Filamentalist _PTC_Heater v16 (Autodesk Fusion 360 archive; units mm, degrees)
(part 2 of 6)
sketch "Sketch153" plane through (-25.4087, 0, 0) normal (-1, 0, 0) x axis (0, -1, 0)
  line L1 (-131.7787, -103.2462) -> (-131.7787, 82.7538)
  line L2 (-127.2387, -103.2462) -> (-131.7787, -103.2462)
  line L3 (-127.2387, 82.7538) -> (-127.2387, -103.2462)
  line L4 (-131.7787, 82.7538) -> (-127.2387, 82.7538)
  line L5 (-64, 4) -> (-133, 4)
  line L6 (-64, 4.01) -> (-64, 4)
  line L7 (-133, 4.01) -> (-64, 4.01)
  line L8 (-133, 4) -> (-133, 4.01)
  point P6 (-133, 4)
  point P9 (-133, 4.01)
  horizontal L5
  vertical L6
  horizontal L7
  vertical L8
  dimension "d493" distance P6 P9 = 0.01
extrude "Extrude31" cut sketch "Sketch153" profile of L1 L3 L5 L6 L7 L8 against normal blind 160
sketch "Sketch154" plane through (0, 131.7787, 0) normal (0, 1, 0) x axis (-1, 0, 0)
  line L1 (25.4087, 4.01) -> (22.6596, 4.01)
  line L2 (25.4087, 82.7538) -> (25.4087, 4.01)
  line L3 (-106.3913, 102.7538) -> (5.4087, 102.7538)
  line L4 (-126.3913, 41.3578) -> (-126.3913, 82.7538)
  line L5 (-126.1913, 41.3578) -> (-126.3913, 41.3578)
  line L6 (-126.1913, 4.01) -> (-126.1913, 41.3578)
  line L7 (-123.4423, 4.01) -> (-126.1913, 4.01)
  line L8 (18.1577, 4.01) -> (-118.9404, 4.01)
  line L9 (-75.4807, 26.9368) -> (-71.2365, 31.181)
  line L10 (-71.2365, 51.5347) -> (-75.4808, 55.779)
  line L11 (-40.3585, 60.7014) -> (-44.602, 56.4579)
  line L12 (-44.602, 26.2578) -> (-40.3585, 22.0143)
  line L13 (-41.0373, 21.3355) -> (-45.2808, 25.579)
  line L14 (-75.4809, 25.579) -> (-79.7243, 21.3355)
  line L15 (-65.6314, 35.4285) -> (-69.8785, 31.1814)
  line L16 (-50.8832, 31.1814) -> (-55.1303, 35.4285)
  line L17 (-55.1317, 45.9282) -> (-59.7021, 41.3578)
  line L18 (-59.7021, 41.3578) -> (-55.1317, 36.7875)
  line L19 (-70.5573, 31.8602) -> (-66.3102, 36.1073)
  line L20 (-66.3102, 46.6084) -> (-70.5573, 50.8555)
  line L21 (-65.63, 36.7875) -> (-61.0596, 41.3578)
  line L22 (-61.0596, 41.3578) -> (-65.63, 45.9282)
  line L23 (-69.8785, 51.5343) -> (-65.6314, 47.2872)
  line L24 (-55.1303, 47.2872) -> (-50.8832, 51.5343)
  line L25 (-64.9512, 46.607) -> (-60.3808, 42.0366)
  line L26 (-60.3808, 42.0366) -> (-55.8105, 46.607)
  line L27 (-45.2808, 57.1367) -> (-41.0373, 61.3802)
  line L28 (-79.7244, 61.3802) -> (-75.4809, 57.1367)
  line L29 (-74.802, 56.4578) -> (-70.5577, 52.2135)
  line L30 (-50.204, 52.2135) -> (-45.9597, 56.4578)
  line L31 (-55.8105, 36.1087) -> (-60.3808, 40.6791)
  line L32 (-60.3808, 40.6791) -> (-64.9512, 36.1087)
  line L33 (-49.5252, 31.181) -> (-45.281, 26.9368)
  line L34 (-45.2809, 55.779) -> (-49.5252, 51.5347)
  line L35 (-70.5577, 30.5022) -> (-74.8019, 26.258)
  line L36 (-45.9598, 26.258) -> (-50.204, 30.5022)
  line L37 (-54.4515, 36.1073) -> (-50.2044, 31.8602)
  line L38 (-50.2044, 50.8555) -> (-54.4515, 46.6084)
  line L39 (-76.1597, 56.4579) -> (-80.4032, 60.7014)
  line L40 (-80.4031, 22.0143) -> (-76.1597, 26.2578)
  line L41 (-88, 44.8573) -> (-88, 37.8584)
  line L42 (4.6087, 88.3538) -> (-105.3913, 88.3538)
  line L43 (4.6087, -241.6462) -> (4.6087, 88.3538)
  line L44 (-105.3913, -241.6462) -> (4.6087, -241.6462)
  line L45 (-105.3913, 88.3538) -> (-105.3913, -241.6462)
  arc A1 centre (5.4087, 82.7538) radius 20 clockwise from (5.4087, 102.7538) to (25.4087, 82.7538)
  arc A2 centre (-106.3913, 82.7538) radius 20 clockwise from (-126.3913, 82.7538) to (-106.3913, 102.7538)
  arc A3 centre (-121.1913, 2.7088) radius 2.6 clockwise from (-123.4423, 4.01) to (-118.9404, 4.01)
  arc A4 centre (20.4087, 2.7088) radius 2.6 clockwise from (18.1577, 4.01) to (22.6596, 4.01)
  circle C1 centre (4.6087, 88.3538) radius 2.6
  arc A5 centre (-105.5913, 88.3538) radius 2.6 clockwise from (-105.4913, 90.9519) to (-105.4913, 85.7557)
  arc A6 centre (-105.3913, 88.3538) radius 2.6 clockwise from (-105.4913, 85.7557) to (-105.4913, 90.9519)
  arc A7 centre (-60.3808, 41.3579) radius 20.88 clockwise from (-75.4807, 26.9368) to (-75.4808, 55.779)
  arc A8 centre (-60.3809, 41.3578) radius 14.88 clockwise from (-71.2365, 31.181) to (-71.2365, 51.5347)
  arc A9 centre (-60.3808, 41.3579) radius 27.84 clockwise from (-40.3585, 60.7014) to (-40.3585, 22.0143)
  arc A10 centre (-60.3809, 41.3578) radius 21.84 clockwise from (-44.602, 56.4579) to (-44.602, 26.2578)
  arc A11 centre (-60.3808, 41.3579) radius 27.84 clockwise from (-41.0373, 21.3355) to (-79.7243, 21.3355)
  arc A12 centre (-60.3809, 41.3578) radius 21.84 clockwise from (-45.2808, 25.579) to (-75.4809, 25.579)
  circle C2 centre (-85.3808, 16.3578) radius 2.2
  arc A13 centre (-60.3808, 41.3579) radius 7.92 clockwise from (-55.1303, 35.4285) to (-65.6314, 35.4285)
  arc A14 centre (-60.3809, 41.3579) radius 13.92 clockwise from (-50.8832, 31.1814) to (-69.8785, 31.1814)
  arc A15 centre (-60.3808, 41.3578) radius 6.96 clockwise from (-55.1317, 45.9282) to (-55.1317, 36.7875)
  arc A16 centre (-60.3809, 41.3579) radius 13.92 clockwise from (-70.5573, 31.8602) to (-70.5573, 50.8555)
  arc A17 centre (-60.3808, 41.3579) radius 7.92 clockwise from (-66.3102, 36.1073) to (-66.3102, 46.6084)
  arc A18 centre (-60.3808, 41.3578) radius 6.96 clockwise from (-65.63, 36.7875) to (-65.63, 45.9282)
  arc A19 centre (-60.3809, 41.3579) radius 13.92 clockwise from (-69.8785, 51.5343) to (-50.8832, 51.5343)
  arc A20 centre (-60.3808, 41.3579) radius 7.92 clockwise from (-65.6314, 47.2872) to (-55.1303, 47.2872)
  arc A21 centre (-60.3808, 41.3578) radius 6.96 clockwise from (-64.9512, 46.607) to (-55.8105, 46.607)
  arc A22 centre (-60.3809, 41.3578) radius 21.84 clockwise from (-75.4809, 57.1367) to (-45.2808, 57.1367)
  arc A23 centre (-60.3808, 41.3579) radius 27.84 clockwise from (-79.7244, 61.3802) to (-41.0373, 61.3802)
  arc A24 centre (-60.3808, 41.3579) radius 20.88 clockwise from (-74.802, 56.4578) to (-45.9597, 56.4578)
  arc A25 centre (-60.3809, 41.3578) radius 14.88 clockwise from (-70.5577, 52.2135) to (-50.204, 52.2135)
  arc A26 centre (-60.3808, 41.3578) radius 6.96 clockwise from (-55.8105, 36.1087) to (-64.9512, 36.1087)
  circle C3 centre (-85.3808, 66.3578) radius 2.2
  circle C4 centre (-35.3808, 66.3578) radius 2.2
  circle C5 centre (-35.3808, 16.3578) radius 2.2
  arc A27 centre (-60.3809, 41.3578) radius 14.88 clockwise from (-49.5252, 51.5347) to (-49.5252, 31.181)
  arc A28 centre (-60.3808, 41.3579) radius 20.88 clockwise from (-45.2809, 55.779) to (-45.281, 26.9368)
  arc A29 centre (-60.3809, 41.3578) radius 14.88 clockwise from (-50.204, 30.5022) to (-70.5577, 30.5022)
  arc A30 centre (-60.3808, 41.3579) radius 20.88 clockwise from (-45.9598, 26.258) to (-74.8019, 26.258)
  arc A31 centre (-60.3808, 41.3579) radius 7.92 clockwise from (-54.4515, 46.6084) to (-54.4515, 36.1073)
  arc A32 centre (-60.3809, 41.3579) radius 13.92 clockwise from (-50.2044, 50.8555) to (-50.2044, 31.8602)
  arc A33 centre (-60.3808, 41.3579) radius 27.84 clockwise from (-88, 44.8573) to (-80.4032, 60.7014)
  arc A34 centre (-60.3809, 41.3578) radius 21.84 clockwise from (-76.1597, 26.2578) to (-76.1597, 56.4579)
  arc A35 centre (-60.3808, 41.3579) radius 27.84 clockwise from (-80.4031, 22.0143) to (-88, 37.8584)
  point P22 (-105.3913, 88.3538)
  point P96 (-105.3913, 88.3538)
  point P99 (-105.3913, -241.6462)
  horizontal L42
  vertical L43
  horizontal L44
  vertical L45
  coincident P22 P96
  dimension "d498" distance P96 P99 = 330
move "Move2"
sketch "Sketch155" plane through (0, 0, -119.5) normal (0, 0, 1) x axis (-1, 0, 0)
  line L1 (10.3687, -85.2967) -> (9.5051, -84.4331)
  line L2 (10.3687, -129.2387) -> (10.3687, -85.2967)
  line L3 (-111.1513, -129.2387) -> (10.3687, -129.2387)
  line L4 (-111.1513, -85.2967) -> (-111.1513, -129.2387)
  line L5 (-110.2877, -84.4331) -> (-111.1513, -85.2967)
  line L6 (-110.2877, -74.3239) -> (-110.2877, -84.4331)
  line L7 (-111.4053, -74.3239) -> (-110.2877, -74.3239)
  line L8 (-111.4053, -72.0887) -> (-111.4053, -74.3239)
  line L9 (-113.8913, -72.0887) -> (-111.4053, -72.0887)
  line L10 (-113.8913, -127.2387) -> (-113.8913, -72.0887)
  line L11 (-118.9346, -127.2387) -> (-113.8913, -127.2387)
  line L12 (-118.9346, -131.7787) -> (-118.9346, -127.2387)
  line L13 (18.152, -131.7787) -> (-118.9346, -131.7787)
  line L14 (18.152, -127.2387) -> (18.152, -131.7787)
  line L15 (12.9087, -127.2387) -> (18.152, -127.2387)
  line L16 (12.9087, -72.0887) -> (12.9087, -127.2387)
  line L17 (10.6227, -72.0887) -> (12.9087, -72.0887)
  line L18 (10.6227, -74.3239) -> (10.6227, -72.0887)
  line L19 (9.5051, -74.3239) -> (10.6227, -74.3239)
  line L20 (9.5051, -84.4331) -> (9.5051, -74.3239)
extrude "Extrude50" new body sketch "Sketch155" along normal blind 123.55
offset_faces "OffsetFaces5" distance 7.257
offset_faces "OffsetFaces6" distance 7.257
offset_faces "OffsetFaces7" distance 0.2
combine "Combine2"
move "Move3"
sketch "Sketch156" plane through (0, 0, -119.5) normal (0, 0, 1) x axis (-1, 0, 0)
  line L1 (10.235, -73.9768) -> (-111.485, -73.9768)
  line L2 (10.235, -71.9956) -> (10.235, -73.9768)
  line L3 (12.775, -71.9956) -> (10.235, -71.9956)
  line L4 (12.775, -70.9796) -> (12.775, -71.9956)
  line L5 (11.759, -69.9636) -> (12.775, -70.9796)
  line L6 (-113.009, -69.9636) -> (11.759, -69.9636)
  line L7 (-114.025, -70.9796) -> (-113.009, -69.9636)
  line L8 (-114.025, -71.9956) -> (-114.025, -70.9796)
  line L9 (-111.485, -71.9956) -> (-114.025, -71.9956)
  line L10 (-111.485, -73.9768) -> (-111.485, -71.9956)
extrude "Extrude51" new body sketch "Sketch156" along normal blind 130
move "Move13"
combine "Combine2"
sketch "Sketch157" plane through (-12.9087, 0, 0) normal (-1, 0, 0) x axis (0, -1, 0)
  line L1 (-85.072, -184.7162) -> (-85.072, -183.0646)
  line L2 (-86.5374, -184.7162) -> (-85.072, -184.7162)
  line L3 (-86.5374, -179.1478) -> (-86.5374, -184.7162)
  line L4 (-85.072, -179.1478) -> (-86.5374, -179.1478)
  line L5 (-85.072, -179.9247) -> (-85.072, -179.1478)
  curve K1 (-83.9654, -179.0501) -> (-85.072, -179.9247)
  curve K2 (-83.1182, -179.3584) -> (-83.9654, -179.0501)
  line L6 (-83.4601, -180.7521) -> (-83.1182, -179.3584)
  curve K3 (-84.1256, -180.5155) -> (-83.4601, -180.7521)
  curve K4 (-85.072, -183.0646) -> (-84.1256, -180.5155)
  line L7 (-99.8083, -184.7162) -> (-98.3735, -184.7162)
  line L8 (-101.582, -179.1478) -> (-99.8083, -184.7162)
  line L9 (-100.1411, -179.1478) -> (-101.582, -179.1478)
  line L10 (-99.0909, -182.7975) -> (-100.1411, -179.1478)
  line L11 (-98.1323, -179.1478) -> (-99.0909, -182.7975)
  line L12 (-96.7051, -179.1478) -> (-98.1323, -179.1478)
  line L13 (-95.7694, -182.7975) -> (-96.7051, -179.1478)
  line L14 (-94.7161, -179.1478) -> (-95.7694, -182.7975)
  line L15 (-93.2782, -179.1478) -> (-94.7161, -179.1478)
  line L16 (-95.0473, -184.7162) -> (-93.2782, -179.1478)
  line L17 (-96.4624, -184.7162) -> (-95.0473, -184.7162)
  line L18 (-97.4301, -181.1352) -> (-96.4624, -184.7162)
  line L19 (-98.3735, -184.7162) -> (-97.4301, -181.1352)
  line L20 (-114.282, -184.7162) -> (-112.8167, -184.7162)
  line L21 (-114.282, -177.0962) -> (-114.282, -184.7162)
  line L22 (-111.8443, -177.0962) -> (-114.282, -177.0962)
  curve K5 (-110.037, -177.2122) -> (-111.8443, -177.0962)
  curve K6 (-108.5182, -179.4607) -> (-110.037, -177.2122)
  curve K7 (-110.2171, -181.7732) -> (-108.5182, -179.4607)
  curve K8 (-111.8138, -181.8831) -> (-110.2171, -181.7732)
  line L23 (-112.8167, -181.8831) -> (-111.8138, -181.8831)
  line L24 (-112.8167, -184.7162) -> (-112.8167, -181.8831)
  curve K9 (-88.7844, -125.8078) -> (-89.7246, -126.5893)
  line L25 (-87.319, -126.0031) -> (-88.7844, -125.8078)
  curve K10 (-89.7216, -127.6639) -> (-87.319, -126.0031)
  curve K11 (-91.8525, -126.7236) -> (-89.7216, -127.6639)
  curve K12 (-92.399, -124.8232) -> (-91.8525, -126.7236)
  curve K13 (-89.8574, -121.9001) -> (-92.399, -124.8232)
  curve K14 (-87.2213, -125.2216) -> (-89.8574, -121.9001)
  line L26 (-90.9336, -125.2216) -> (-87.2213, -125.2216)
  curve K15 (-89.7246, -126.5893) -> (-90.9336, -125.2216)
  curve K16 (-100.312, -123.6585) -> (-99.3992, -122.9747)
  line L27 (-101.582, -123.4631) -> (-100.312, -123.6585)
  curve K17 (-99.2527, -121.9001) -> (-101.582, -123.4631)
  curve K18 (-96.9905, -124.034) -> (-99.2527, -121.9001)
  line L28 (-96.9905, -125.7452) -> (-96.9905, -124.034)
  curve K19 (-96.5997, -127.5662) -> (-96.9905, -125.7452)
  line L29 (-98.0651, -127.5662) -> (-96.5997, -127.5662)
  curve K20 (-98.204, -127.0991) -> (-98.0651, -127.5662)
  curve K21 (-98.2559, -126.9144) -> (-98.204, -127.0991)
  curve K22 (-99.9549, -127.6639) -> (-98.2559, -126.9144)
  curve K23 (-101.7774, -125.9955) -> (-99.9549, -127.6639)
  curve K24 (-99.8297, -124.2203) -> (-101.7774, -125.9955)
  curve K25 (-98.4559, -123.8539) -> (-99.8297, -124.2203)
  line L30 (-98.4559, -123.715) -> (-98.4559, -123.8539)
  curve K26 (-99.3992, -122.9747) -> (-98.4559, -123.715)
  line L31 (-114.7705, -127.5662) -> (-113.3051, -127.5662)
  line L32 (-114.7705, -119.9462) -> (-114.7705, -127.5662)
  line L33 (-113.3051, -119.9462) -> (-114.7705, -119.9462)
  line L34 (-113.3051, -122.9747) -> (-113.3051, -119.9462)
  line L35 (-110.179, -122.9747) -> (-113.3051, -122.9747)
  line L36 (-110.179, -119.9462) -> (-110.179, -122.9747)
  line L37 (-108.7136, -119.9462) -> (-110.179, -119.9462)
  line L38 (-108.7136, -127.5662) -> (-108.7136, -119.9462)
  line L39 (-110.179, -127.5662) -> (-108.7136, -127.5662)
  line L40 (-110.179, -124.2447) -> (-110.179, -127.5662)
  line L41 (-113.3051, -124.2447) -> (-110.179, -124.2447)
  line L42 (-113.3051, -127.5662) -> (-113.3051, -124.2447)
  curve K27 (-104.0244, -125.8078) -> (-104.9646, -126.5893)
  line L43 (-102.559, -126.0031) -> (-104.0244, -125.8078)
  curve K28 (-104.9616, -127.6639) -> (-102.559, -126.0031)
  curve K29 (-107.0925, -126.7236) -> (-104.9616, -127.6639)
  curve K30 (-107.639, -124.8232) -> (-107.0925, -126.7236)
  curve K31 (-105.0974, -121.9001) -> (-107.639, -124.8232)
  curve K32 (-102.4613, -125.2216) -> (-105.0974, -121.9001)
  line L44 (-106.1736, -125.2216) -> (-102.4613, -125.2216)
  curve K33 (-104.9646, -126.5893) -> (-106.1736, -125.2216)
  line L45 (-92.7897, -121.9978) -> (-93.8644, -121.9978)
  line L46 (-92.7897, -123.0724) -> (-92.7897, -121.9978)
  line L47 (-93.8644, -123.0724) -> (-92.7897, -123.0724)
  line L48 (-93.8644, -125.4658) -> (-93.8644, -123.0724)
  curve K34 (-93.4461, -126.5893) -> (-93.8644, -125.4658)
  curve K35 (-92.8386, -126.4489) -> (-93.4461, -126.5893)
  line L49 (-92.692, -127.4701) -> (-92.8386, -126.4489)
  curve K36 (-93.8705, -127.6639) -> (-92.692, -127.4701)
  curve K37 (-95.2824, -126.5939) -> (-93.8705, -127.6639)
  curve K38 (-95.3297, -125.5391) -> (-95.2824, -126.5939)
  line L50 (-95.3297, -123.0724) -> (-95.3297, -125.5391)
  line L51 (-96.0136, -123.0724) -> (-95.3297, -123.0724)
  line L52 (-96.0136, -121.9978) -> (-96.0136, -123.0724)
  line L53 (-95.3297, -121.9978) -> (-96.0136, -121.9978)
  line L54 (-95.3297, -120.9231) -> (-95.3297, -121.9978)
  line L55 (-93.8644, -120.0439) -> (-95.3297, -120.9231)
  line L56 (-93.8644, -121.9978) -> (-93.8644, -120.0439)
  line L57 (-84.5836, -127.5662) -> (-84.5836, -125.9146)
  line L58 (-86.049, -127.5662) -> (-84.5836, -127.5662)
  line L59 (-86.049, -121.9978) -> (-86.049, -127.5662)
  line L60 (-84.5836, -121.9978) -> (-86.049, -121.9978)
  line L61 (-84.5836, -122.7747) -> (-84.5836, -121.9978)
  curve K39 (-83.4769, -121.9001) -> (-84.5836, -122.7747)
  curve K40 (-82.6297, -122.2084) -> (-83.4769, -121.9001)
  line L62 (-82.9717, -123.6021) -> (-82.6297, -122.2084)
  curve K41 (-83.6372, -123.3655) -> (-82.9717, -123.6021)
  curve K42 (-84.5836, -125.9146) -> (-83.6372, -123.3655)
  curve K43 (-107.639, -181.8541) -> (-104.8013, -184.8139)
  curve K44 (-104.8105, -179.0501) -> (-107.639, -181.8541)
  curve K45 (-101.9728, -181.9167) -> (-104.8105, -179.0501)
  curve K46 (-104.8013, -184.8139) -> (-101.9728, -181.9167)
  curve K47 (-89.2728, -182.9578) -> (-90.2131, -183.7393)
  line L63 (-87.8074, -183.1531) -> (-89.2728, -182.9578)
  curve K48 (-90.21, -184.8139) -> (-87.8074, -183.1531)
  curve K49 (-92.341, -183.8736) -> (-90.21, -184.8139)
  curve K50 (-92.8874, -181.9732) -> (-92.341, -183.8736)
  curve K51 (-90.3459, -179.0501) -> (-92.8874, -181.9732)
  curve K52 (-87.7097, -182.3716) -> (-90.3459, -179.0501)
  line L64 (-91.422, -182.3716) -> (-87.7097, -182.3716)
  curve K53 (-90.2131, -183.7393) -> (-91.422, -182.3716)
  line L65 (-72.0887, 73.7538) -> (-72.0887, -226.7462)
  line L66 (-127.2387, 73.7538) -> (-72.0887, 73.7538)
  line L67 (-127.2387, -226.7462) -> (-127.2387, 73.7538)
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extrude "Extrude32" cut sketch "Sketch157" against normal blind 10
copy_paste_bodies "CopyPasteBodies5"
move "Move14"
component_insert "Component Insert16"
position "Position8"
sketch "Sketch158" plane through (0, 129.2387, 0) normal (0, -1, 0) x axis (1, 0, 0)
  line L1 (111.1513, 73.7538) -> (111.1513, -226.7462)
  line L2 (-5.4087, 78.7138) -> (106.1913, 78.7138)
  line L3 (-10.3687, 55.8538) -> (-10.3687, 73.7538)
  line L4 (-7.8287, 55.8538) -> (-10.3687, 55.8538)
  line L5 (-7.8287, 22.1988) -> (-7.8287, 55.8538)
  line L6 (-10.3687, 22.1988) -> (-7.8287, 22.1988)
  line L7 (-10.3687, -130.4872) -> (-10.3687, 22.1988)
  line L8 (-4.5267, -130.4872) -> (-10.3687, -130.4872)
  line L9 (-4.5267, -160.2052) -> (-4.5267, -130.4872)
  line L10 (-10.3687, -160.2052) -> (-4.5267, -160.2052)
  line L11 (-10.3687, -187.6372) -> (-10.3687, -160.2052)
  line L12 (-4.5267, -187.6372) -> (-10.3687, -187.6372)
  line L13 (-4.5267, -217.3552) -> (-4.5267, -187.6372)
  line L14 (-10.3687, -217.3552) -> (-4.5267, -217.3552)
  line L15 (-10.3687, -226.7462) -> (-10.3687, -217.3552)
  line L16 (106.1913, -231.7062) -> (-5.4087, -231.7062)
  line L17 (76.1597, 26.2578) -> (80.4031, 22.0143)
  line L18 (80.4032, 60.7014) -> (76.1597, 56.4579)
  line L19 (88, 37.8584) -> (88, 44.8573)
  line L20 (50.2044, 31.8602) -> (54.4515, 36.1073)
  line L21 (54.4515, 46.6084) -> (50.2044, 50.8555)
  line L22 (74.8019, 26.258) -> (70.5577, 30.5022)
  line L23 (50.204, 30.5022) -> (45.9598, 26.258)
  line L24 (45.281, 26.9368) -> (49.5252, 31.181)
  line L25 (49.5252, 51.5347) -> (45.2809, 55.779)
  line L26 (60.3808, 40.6791) -> (55.8105, 36.1087)
  line L27 (64.9512, 36.1087) -> (60.3808, 40.6791)
  line L28 (70.5577, 52.2135) -> (74.802, 56.4578)
  line L29 (45.9597, 56.4578) -> (50.204, 52.2135)
  line L30 (41.0373, 61.3802) -> (45.2808, 57.1367)
  line L31 (75.4809, 57.1367) -> (79.7244, 61.3802)
  line L32 (60.3808, 42.0366) -> (64.9512, 46.607)
  line L33 (55.8105, 46.607) -> (60.3808, 42.0366)
  line L34 (65.6314, 47.2872) -> (69.8785, 51.5343)
  line L35 (50.8832, 51.5343) -> (55.1303, 47.2872)
  line L36 (61.0596, 41.3578) -> (65.63, 36.7875)
  line L37 (65.63, 45.9282) -> (61.0596, 41.3578)
  line L38 (66.3102, 36.1073) -> (70.5573, 31.8602)
  line L39 (70.5573, 50.8555) -> (66.3102, 46.6084)
  line L40 (59.7021, 41.3578) -> (55.1317, 45.9282)
  line L41 (55.1317, 36.7875) -> (59.7021, 41.3578)
  line L42 (69.8785, 31.1814) -> (65.6314, 35.4285)
  line L43 (55.1303, 35.4285) -> (50.8832, 31.1814)
  line L44 (45.2808, 25.579) -> (41.0373, 21.3355)
  line L45 (79.7243, 21.3355) -> (75.4809, 25.579)
  line L46 (44.602, 56.4579) -> (40.3585, 60.7014)
  line L47 (40.3585, 22.0143) -> (44.602, 26.2578)
  line L48 (71.2365, 31.181) -> (75.4807, 26.9368)
  line L49 (75.4808, 55.779) -> (71.2365, 51.5347)
  circle C1 centre (26.6464, -197.4162) radius 3.175
  circle C2 centre (34.3453, -192.9712) radius 3.175
  circle C3 centre (26.6464, -179.6362) radius 3.175
  circle C4 centre (26.6464, -188.5262) radius 3.175
  circle C5 centre (18.9474, -192.9712) radius 3.175
  circle C6 centre (3.5495, -210.7512) radius 3.175
  circle C7 centre (11.2484, -206.3062) radius 3.175
  circle C8 centre (18.9474, -201.8612) radius 3.175
  circle C9 centre (18.9474, -219.6412) radius 3.175
  circle C10 centre (34.3453, -210.7512) radius 3.175
  circle C11 centre (42.0443, -197.4162) radius 3.175
  circle C12 centre (42.0443, -188.5262) radius 3.175
  circle C13 centre (3.5495, -219.6412) radius 3.175
  circle C14 centre (11.2484, -215.1962) radius 3.175
  circle C15 centre (3.5495, -166.3012) radius 3.175
  circle C16 centre (3.5495, -175.1912) radius 3.175
  circle C17 centre (18.9474, -157.4112) radius 3.175
  circle C18 centre (18.9474, -166.3012) radius 3.175
  circle C19 centre (11.2484, -170.7462) radius 3.175
  circle C20 centre (11.2484, -179.6362) radius 3.175
  circle C21 centre (11.2484, -144.0762) radius 3.175
  circle C22 centre (3.5495, -148.5212) radius 3.175
  circle C23 centre (11.2484, -161.8562) radius 3.175
  circle C24 centre (11.2484, -152.9662) radius 3.175
  circle C25 centre (18.9474, -148.5212) radius 3.175
  circle C26 centre (3.5495, -157.4112) radius 3.175
  circle C27 centre (3.5495, -201.8612) radius 3.175
  circle C28 centre (11.2484, -197.4162) radius 3.175
  circle C29 centre (11.2484, -188.5262) radius 3.175
  circle C30 centre (18.9474, -184.0812) radius 3.175
  circle C31 centre (3.5495, -184.0812) radius 3.175
  circle C32 centre (3.5495, -192.9712) radius 3.175
  circle C33 centre (26.6464, -161.8562) radius 3.175
  circle C34 centre (26.6464, -170.7462) radius 3.175
  circle C35 centre (18.9474, -175.1912) radius 3.175
  circle C36 centre (11.2484, -224.0862) radius 3.175
  circle C37 centre (49.7433, -166.3012) radius 3.175
  circle C38 centre (49.7433, -175.1912) radius 3.175
  circle C39 centre (57.4422, -170.7462) radius 3.175
  circle C40 centre (57.4422, -161.8562) radius 3.175
  circle C41 centre (65.1412, -157.4112) radius 3.175
  circle C42 centre (65.1412, -148.5212) radius 3.175
  circle C43 centre (26.6464, -144.0762) radius 3.175
  circle C44 centre (42.0443, -152.9662) radius 3.175
  circle C45 centre (42.0443, -144.0762) radius 3.175
  circle C46 centre (34.3453, -148.5212) radius 3.175
  circle C47 centre (34.3453, -157.4112) radius 3.175
  circle C48 centre (26.6464, -152.9662) radius 3.175
  circle C49 centre (49.7433, -184.0812) radius 3.175
  circle C50 centre (34.3453, -166.3012) radius 3.175
  circle C51 centre (42.0443, -179.6362) radius 3.175
  circle C52 centre (26.5037, -224.0859) radius 3.175
  arc A1 centre (26.6058, -215.1959) radius 3.175 clockwise from (26.6021, -218.3709) to (26.65, -212.0212)
  arc A2 centre (26.6464, -215.1962) radius 3.175 clockwise from (26.65, -212.0212) to (26.6021, -218.3709)
  arc A3 centre (18.9068, -210.7509) radius 3.175 clockwise from (18.9032, -213.9259) to (18.9511, -207.5762)
  arc A4 centre (18.9474, -210.7512) radius 3.175 clockwise from (18.9511, -207.5762) to (18.9032, -213.9259)
  arc A5 centre (26.6058, -206.3059) radius 3.175 clockwise from (26.6021, -209.4809) to (26.65, -203.1312)
  arc A6 centre (26.6464, -206.3062) radius 3.175 clockwise from (26.65, -203.1312) to (26.6021, -209.4809)
  arc A7 centre (34.3047, -201.8609) radius 3.175 clockwise from (34.3011, -205.0359) to (34.349, -198.6862)
  arc A8 centre (34.3453, -201.8612) radius 3.175 clockwise from (34.349, -198.6862) to (34.3011, -205.0359)
  arc A9 centre (34.3089, -184.0809) radius 3.175 clockwise from (34.3004, -187.2559) to (34.3538, -180.9062)
  arc A10 centre (34.3453, -184.0812) radius 3.175 clockwise from (34.3538, -180.9062) to (34.3004, -187.2559)
  arc A11 centre (34.3089, -175.1909) radius 3.175 clockwise from (34.3004, -178.3659) to (34.3538, -172.0162)
  arc A12 centre (34.3453, -175.1912) radius 3.175 clockwise from (34.3538, -172.0162) to (34.3004, -178.3659)
  arc A13 centre (42.0078, -170.7459) radius 3.175 clockwise from (41.9994, -173.9209) to (42.0527, -167.5712)
  arc A14 centre (42.0443, -170.7462) radius 3.175 clockwise from (42.0527, -167.5712) to (41.9994, -173.9209)
  arc A15 centre (42.0078, -161.8559) radius 3.175 clockwise from (41.9994, -165.0309) to (42.0527, -158.6812)
  arc A16 centre (42.0443, -161.8562) radius 3.175 clockwise from (42.0527, -158.6812) to (41.9994, -165.0309)
  arc A17 centre (49.7068, -148.5209) radius 3.175 clockwise from (49.6984, -151.6959) to (49.7517, -145.3462)
  arc A18 centre (49.7433, -148.5212) radius 3.175 clockwise from (49.7517, -145.3462) to (49.6984, -151.6959)
  arc A19 centre (57.4058, -144.0759) radius 3.175 clockwise from (57.3973, -147.2509) to (57.4507, -140.9012)
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sketch "Sketch159" plane through (-12.9087, 0, 0) normal (-1, 0, 0) x axis (0, -1, 0)
  circle C1 centre (-99.1397, -88.4962) radius 16.5355
  circle C2 centre (-99.1397, -88.4962) radius 15.621
  circle C3 centre (-99.1397, -88.4962) radius 16.5355
  circle C4 centre (-99.1397, -88.4962) radius 16.5
  concentric C1 C3
  concentric C3 C4
  dimension "d508" diameter C4 = 33
extrude "Extrude33" cut sketch "Sketch159" profile of C2 C4 against normal blind 7
combine "Combine3"
sketch "Sketch160" plane through (-4.5267, 0, 0) normal (1, 0, 0) x axis (0, 1, 0)
  line L1 (129.2387, -217.3552) -> (107.4656, -217.3552)
  line L2 (129.2387, -187.6372) -> (129.2387, -217.3552)
  line L3 (107.4656, -187.6372) -> (129.2387, -187.6372)
  line L4 (80.5196, -187.6372) -> (124.6456, -187.6372)
  line L5 (80.5196, -217.3552) -> (80.5196, -187.6372)
  line L6 (124.6456, -217.3552) -> (80.5196, -217.3552)
  line L7 (124.6456, -187.6372) -> (124.6456, -217.3552)
  arc A1 centre (99.1397, -202.4962) radius 17.0326 clockwise from (107.4656, -187.6372) to (107.4656, -217.3552)
  circle C1 centre (99.1397, -202.4962) radius 17.0326
  circle C2 centre (99.1397, -202.4962) radius 14.859
  point P8 (124.6456, -187.6372)
  horizontal L4
  vertical L5
  horizontal L6
  vertical L7
  coincident L3 P8
  concentric C1 C2
  tangent L4 C2
extrude "Extrude34" add sketch "Sketch160" profile of A1 L1 L3 C1 L4 L6 L7 C2 against normal blind 5.842
sketch "Sketch161" plane through (-12.9087, 0, 0) normal (-1, 0, 0) x axis (0, -1, 0)
  line L1 (-124.3873, 24.4213) -> (-76.1273, 24.4213)
  line L2 (-124.3873, 53.6313) -> (-124.3873, 24.4213)
  line L3 (-76.1273, 53.6313) -> (-124.3873, 53.6313)
  line L4 (-76.1273, 24.4213) -> (-76.1273, 53.6313)
  line L5 (-72.0887, 73.7538) -> (-72.0887, -226.7462)
  line L6 (-127.2387, 73.7538) -> (-72.0887, 73.7538)
  line L7 (-127.2387, -226.7462) -> (-127.2387, 73.7538)
  line L8 (-72.0887, -226.7462) -> (-127.2387, -226.7462)
  curve K1 (-89.2728, -182.9578) -> (-90.2131, -183.7393)
  line L9 (-87.8074, -183.1531) -> (-89.2728, -182.9578)
  curve K2 (-90.21, -184.8139) -> (-87.8074, -183.1531)
  curve K3 (-92.341, -183.8736) -> (-90.21, -184.8139)
  curve K4 (-92.8874, -181.9732) -> (-92.341, -183.8736)
  curve K5 (-90.3459, -179.0501) -> (-92.8874, -181.9732)
  curve K6 (-87.7097, -182.3716) -> (-90.3459, -179.0501)
  line L10 (-91.422, -182.3716) -> (-87.7097, -182.3716)
  curve K7 (-90.2131, -183.7393) -> (-91.422, -182.3716)
  curve K8 (-107.639, -181.8541) -> (-104.8013, -184.8139)
  curve K9 (-104.8105, -179.0501) -> (-107.639, -181.8541)
  curve K10 (-101.9728, -181.9167) -> (-104.8105, -179.0501)
  curve K11 (-104.8013, -184.8139) -> (-101.9728, -181.9167)
  line L11 (-84.5836, -127.5662) -> (-84.5836, -125.9146)
  line L12 (-86.049, -127.5662) -> (-84.5836, -127.5662)
  line L13 (-86.049, -121.9978) -> (-86.049, -127.5662)
  line L14 (-84.5836, -121.9978) -> (-86.049, -121.9978)
  line L15 (-84.5836, -122.7747) -> (-84.5836, -121.9978)
  curve K12 (-83.4769, -121.9001) -> (-84.5836, -122.7747)
  curve K13 (-82.6297, -122.2084) -> (-83.4769, -121.9001)
  line L16 (-82.9717, -123.6021) -> (-82.6297, -122.2084)
  curve K14 (-83.6372, -123.3655) -> (-82.9717, -123.6021)
  curve K15 (-84.5836, -125.9146) -> (-83.6372, -123.3655)
  line L17 (-92.7897, -121.9978) -> (-93.8644, -121.9978)
  line L18 (-92.7897, -123.0724) -> (-92.7897, -121.9978)
  line L19 (-93.8644, -123.0724) -> (-92.7897, -123.0724)
  line L20 (-93.8644, -125.4658) -> (-93.8644, -123.0724)
  curve K16 (-93.4461, -126.5893) -> (-93.8644, -125.4658)
  curve K17 (-92.8386, -126.4489) -> (-93.4461, -126.5893)
  line L21 (-92.692, -127.4701) -> (-92.8386, -126.4489)
  curve K18 (-93.8705, -127.6639) -> (-92.692, -127.4701)
  curve K19 (-95.2824, -126.5939) -> (-93.8705, -127.6639)
  curve K20 (-95.3297, -125.5391) -> (-95.2824, -126.5939)
  line L22 (-95.3297, -123.0724) -> (-95.3297, -125.5391)
  line L23 (-96.0136, -123.0724) -> (-95.3297, -123.0724)
  line L24 (-96.0136, -121.9978) -> (-96.0136, -123.0724)
  line L25 (-95.3297, -121.9978) -> (-96.0136, -121.9978)
  line L26 (-95.3297, -120.9231) -> (-95.3297, -121.9978)
  line L27 (-93.8644, -120.0439) -> (-95.3297, -120.9231)
  line L28 (-93.8644, -121.9978) -> (-93.8644, -120.0439)
  curve K21 (-104.0244, -125.8078) -> (-104.9646, -126.5893)
  line L29 (-102.559, -126.0031) -> (-104.0244, -125.8078)
  curve K22 (-104.9616, -127.6639) -> (-102.559, -126.0031)
  curve K23 (-107.0925, -126.7236) -> (-104.9616, -127.6639)
  curve K24 (-107.639, -124.8232) -> (-107.0925, -126.7236)
  curve K25 (-105.0974, -121.9001) -> (-107.639, -124.8232)
  curve K26 (-102.4613, -125.2216) -> (-105.0974, -121.9001)
  line L30 (-106.1736, -125.2216) -> (-102.4613, -125.2216)
  curve K27 (-104.9646, -126.5893) -> (-106.1736, -125.2216)
  line L31 (-114.7705, -127.5662) -> (-113.3051, -127.5662)
  line L32 (-114.7705, -119.9462) -> (-114.7705, -127.5662)
  line L33 (-113.3051, -119.9462) -> (-114.7705, -119.9462)
  line L34 (-113.3051, -122.9747) -> (-113.3051, -119.9462)
  line L35 (-110.179, -122.9747) -> (-113.3051, -122.9747)
  line L36 (-110.179, -119.9462) -> (-110.179, -122.9747)
  line L37 (-108.7136, -119.9462) -> (-110.179, -119.9462)
  line L38 (-108.7136, -127.5662) -> (-108.7136, -119.9462)
  line L39 (-110.179, -127.5662) -> (-108.7136, -127.5662)
  line L40 (-110.179, -124.2447) -> (-110.179, -127.5662)
  line L41 (-113.3051, -124.2447) -> (-110.179, -124.2447)
  line L42 (-113.3051, -127.5662) -> (-113.3051, -124.2447)
  curve K28 (-100.312, -123.6585) -> (-99.3992, -122.9747)
  line L43 (-101.582, -123.4631) -> (-100.312, -123.6585)
  curve K29 (-99.2527, -121.9001) -> (-101.582, -123.4631)
  curve K30 (-96.9905, -124.034) -> (-99.2527, -121.9001)
  line L44 (-96.9905, -125.7452) -> (-96.9905, -124.034)
  curve K31 (-96.5997, -127.5662) -> (-96.9905, -125.7452)
  line L45 (-98.0651, -127.5662) -> (-96.5997, -127.5662)
  curve K32 (-98.204, -127.0991) -> (-98.0651, -127.5662)
  curve K33 (-98.2559, -126.9144) -> (-98.204, -127.0991)
  curve K34 (-99.9549, -127.6639) -> (-98.2559, -126.9144)
  curve K35 (-101.7774, -125.9955) -> (-99.9549, -127.6639)
  curve K36 (-99.8297, -124.2203) -> (-101.7774, -125.9955)
  curve K37 (-98.4559, -123.8539) -> (-99.8297, -124.2203)
  line L46 (-98.4559, -123.715) -> (-98.4559, -123.8539)
  curve K38 (-99.3992, -122.9747) -> (-98.4559, -123.715)
  curve K39 (-88.7844, -125.8078) -> (-89.7246, -126.5893)
  line L47 (-87.319, -126.0031) -> (-88.7844, -125.8078)
  curve K40 (-89.7216, -127.6639) -> (-87.319, -126.0031)
  curve K41 (-91.8525, -126.7236) -> (-89.7216, -127.6639)
  curve K42 (-92.399, -124.8232) -> (-91.8525, -126.7236)
  curve K43 (-89.8574, -121.9001) -> (-92.399, -124.8232)
  curve K44 (-87.2213, -125.2216) -> (-89.8574, -121.9001)
  line L48 (-90.9336, -125.2216) -> (-87.2213, -125.2216)
  curve K45 (-89.7246, -126.5893) -> (-90.9336, -125.2216)
  line L49 (-114.282, -184.7162) -> (-112.8167, -184.7162)
  line L50 (-114.282, -177.0962) -> (-114.282, -184.7162)
  line L51 (-111.8443, -177.0962) -> (-114.282, -177.0962)
  curve K46 (-110.037, -177.2122) -> (-111.8443, -177.0962)
  curve K47 (-108.5182, -179.4607) -> (-110.037, -177.2122)
  curve K48 (-110.2171, -181.7732) -> (-108.5182, -179.4607)
  curve K49 (-111.8138, -181.8831) -> (-110.2171, -181.7732)
  line L52 (-112.8167, -181.8831) -> (-111.8138, -181.8831)
  line L53 (-112.8167, -184.7162) -> (-112.8167, -181.8831)
  line L54 (-99.8083, -184.7162) -> (-98.3735, -184.7162)
  line L55 (-101.582, -179.1478) -> (-99.8083, -184.7162)
  line L56 (-100.1411, -179.1478) -> (-101.582, -179.1478)
  line L57 (-99.0909, -182.7975) -> (-100.1411, -179.1478)
  line L58 (-98.1323, -179.1478) -> (-99.0909, -182.7975)
  line L59 (-96.7051, -179.1478) -> (-98.1323, -179.1478)
  line L60 (-95.7694, -182.7975) -> (-96.7051, -179.1478)
  line L61 (-94.7161, -179.1478) -> (-95.7694, -182.7975)
  line L62 (-93.2782, -179.1478) -> (-94.7161, -179.1478)
  line L63 (-95.0473, -184.7162) -> (-93.2782, -179.1478)
  line L64 (-96.4624, -184.7162) -> (-95.0473, -184.7162)
  line L65 (-97.4301, -181.1352) -> (-96.4624, -184.7162)
  line L66 (-98.3735, -184.7162) -> (-97.4301, -181.1352)
  line L67 (-85.072, -184.7162) -> (-85.072, -183.0646)
  line L68 (-86.5374, -184.7162) -> (-85.072, -184.7162)
  line L69 (-86.5374, -179.1478) -> (-86.5374, -184.7162)
  line L70 (-85.072, -179.1478) -> (-86.5374, -179.1478)
  line L71 (-85.072, -179.9247) -> (-85.072, -179.1478)
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extrude "Extrude35" add sketch "Sketch161" against normal blind 2.54
sketch "Sketch162" plane through (-9.5051, 0, 0) normal (1, 0, 0) x axis (0, 1, 0)
  line L1 (84.4331, -147.4689) -> (84.4331, -193.904)
  line L2 (74.3239, -143.3262) -> (84.4187, -143.3262)
  line L3 (74.3239, -222.8162) -> (74.3239, -143.3262)
  line L4 (84.4331, -222.8162) -> (74.3239, -222.8162)
  line L5 (84.4331, -211.0884) -> (84.4331, -222.8162)
  line L6 (79, -189.0814) -> (84.4331, -189.0814)
  line L7 (79, -216) -> (79, -189.0814)
  line L8 (84.4331, -216) -> (79, -216)
  line L9 (84.4331, -189.0814) -> (84.4331, -216)
  arc A1 centre (99.1397, -202.4962) radius 17.0326 clockwise from (84.4331, -211.0884) to (84.4331, -193.904)
  arc A2 centre (99.1397, -145.3462) radius 14.859 clockwise from (84.4331, -147.4689) to (84.4187, -143.3262)
  point P11 (84.4331, -189.0814)
  horizontal L6
  vertical L7
  horizontal L8
  vertical L9
  coincident L1 P11
extrude "Extrude36" add sketch "Sketch162" profile of A1 L1 L5 L6 L7 L8 L9 against normal blind 2
delete_face "DeleteFace17"
delete_face "DeleteFace18"
sketch "Sketch163" plane through (-4.5267, 0, 0) normal (1, 0, 0) x axis (0, 1, 0)
  line L1 (129.2387, -130.4872) -> (129.2387, -160.2052)
  line L2 (99.1397, -130.4872) -> (129.2387, -130.4872)
  line L3 (129.2387, -160.2052) -> (99.1397, -160.2052)
  line L4 (109.8077, -146.5527) -> (109.8077, -144.1397)
  line L5 (108.972, -146.5527) -> (109.8077, -146.5527)
  line L6 (109.8077, -144.1397) -> (108.972, -144.1397)
  arc A1 centre (99.1397, -145.3462) radius 14.859 clockwise from (99.1397, -160.2052) to (99.1397, -130.4872)
  arc A2 centre (99.1397, -145.3462) radius 9.906 clockwise from (108.972, -146.5527) to (108.972, -144.1397)
extrude "Extrude52" new body sketch "Sketch163" against normal blind 5.842
move "Move15"
combine "Combine4"
sketch "Sketch164" plane through (-12.9087, 0, 0) normal (-1, 0, 0) x axis (0, -1, 0)
  line L1 (-124.3873, 24.4213) -> (-76.1273, 24.4213)
  line L2 (-124.3873, 53.6313) -> (-124.3873, 24.4213)
  line L3 (-76.1273, 53.6313) -> (-124.3873, 53.6313)
  line L4 (-76.1273, 24.4213) -> (-76.1273, 53.6313)
  line L5 (-72.0887, 73.7538) -> (-72.0887, -226.7462)
  line L6 (-127.2387, 73.7538) -> (-72.0887, 73.7538)
  line L7 (-127.2387, -226.7462) -> (-127.2387, 73.7538)
  line L8 (-72.0887, -226.7462) -> (-127.2387, -226.7462)
  curve K1 (-89.2728, -182.9578) -> (-90.2131, -183.7393)
  line L9 (-87.8074, -183.1531) -> (-89.2728, -182.9578)
  curve K2 (-90.21, -184.8139) -> (-87.8074, -183.1531)
  curve K3 (-92.341, -183.8736) -> (-90.21, -184.8139)
  curve K4 (-92.8874, -181.9732) -> (-92.341, -183.8736)
  curve K5 (-90.3459, -179.0501) -> (-92.8874, -181.9732)
  curve K6 (-87.7097, -182.3716) -> (-90.3459, -179.0501)
  line L10 (-91.422, -182.3716) -> (-87.7097, -182.3716)
  curve K7 (-90.2131, -183.7393) -> (-91.422, -182.3716)
  curve K8 (-107.639, -181.8541) -> (-104.8013, -184.8139)
  curve K9 (-104.8105, -179.0501) -> (-107.639, -181.8541)
  curve K10 (-101.9728, -181.9167) -> (-104.8105, -179.0501)
  curve K11 (-104.8013, -184.8139) -> (-101.9728, -181.9167)
  line L11 (-84.5836, -127.5662) -> (-84.5836, -125.9146)
  line L12 (-86.049, -127.5662) -> (-84.5836, -127.5662)
  line L13 (-86.049, -121.9978) -> (-86.049, -127.5662)
  line L14 (-84.5836, -121.9978) -> (-86.049, -121.9978)
  line L15 (-84.5836, -122.7747) -> (-84.5836, -121.9978)
  curve K12 (-83.4769, -121.9001) -> (-84.5836, -122.7747)
  curve K13 (-82.6297, -122.2084) -> (-83.4769, -121.9001)
  line L16 (-82.9717, -123.6021) -> (-82.6297, -122.2084)
  curve K14 (-83.6372, -123.3655) -> (-82.9717, -123.6021)
  curve K15 (-84.5836, -125.9146) -> (-83.6372, -123.3655)
  line L17 (-92.7897, -121.9978) -> (-93.8644, -121.9978)
  line L18 (-92.7897, -123.0724) -> (-92.7897, -121.9978)
  line L19 (-93.8644, -123.0724) -> (-92.7897, -123.0724)
  line L20 (-93.8644, -125.4658) -> (-93.8644, -123.0724)
  curve K16 (-93.4461, -126.5893) -> (-93.8644, -125.4658)
  curve K17 (-92.8386, -126.4489) -> (-93.4461, -126.5893)
  line L21 (-92.692, -127.4701) -> (-92.8386, -126.4489)
  curve K18 (-93.8705, -127.6639) -> (-92.692, -127.4701)
  curve K19 (-95.2824, -126.5939) -> (-93.8705, -127.6639)
  curve K20 (-95.3297, -125.5391) -> (-95.2824, -126.5939)
  line L22 (-95.3297, -123.0724) -> (-95.3297, -125.5391)
  line L23 (-96.0136, -123.0724) -> (-95.3297, -123.0724)
  line L24 (-96.0136, -121.9978) -> (-96.0136, -123.0724)
  line L25 (-95.3297, -121.9978) -> (-96.0136, -121.9978)
  line L26 (-95.3297, -120.9231) -> (-95.3297, -121.9978)
  line L27 (-93.8644, -120.0439) -> (-95.3297, -120.9231)
  line L28 (-93.8644, -121.9978) -> (-93.8644, -120.0439)
  curve K21 (-104.0244, -125.8078) -> (-104.9646, -126.5893)
  line L29 (-102.559, -126.0031) -> (-104.0244, -125.8078)
  curve K22 (-104.9616, -127.6639) -> (-102.559, -126.0031)
  curve K23 (-107.0925, -126.7236) -> (-104.9616, -127.6639)
  curve K24 (-107.639, -124.8232) -> (-107.0925, -126.7236)
  curve K25 (-105.0974, -121.9001) -> (-107.639, -124.8232)
  curve K26 (-102.4613, -125.2216) -> (-105.0974, -121.9001)
  line L30 (-106.1736, -125.2216) -> (-102.4613, -125.2216)
  curve K27 (-104.9646, -126.5893) -> (-106.1736, -125.2216)
  line L31 (-114.7705, -127.5662) -> (-113.3051, -127.5662)
  line L32 (-114.7705, -119.9462) -> (-114.7705, -127.5662)
  line L33 (-113.3051, -119.9462) -> (-114.7705, -119.9462)
  line L34 (-113.3051, -122.9747) -> (-113.3051, -119.9462)
  line L35 (-110.179, -122.9747) -> (-113.3051, -122.9747)
  line L36 (-110.179, -119.9462) -> (-110.179, -122.9747)
  line L37 (-108.7136, -119.9462) -> (-110.179, -119.9462)
  line L38 (-108.7136, -127.5662) -> (-108.7136, -119.9462)
  line L39 (-110.179, -127.5662) -> (-108.7136, -127.5662)
  line L40 (-110.179, -124.2447) -> (-110.179, -127.5662)
  line L41 (-113.3051, -124.2447) -> (-110.179, -124.2447)
  line L42 (-113.3051, -127.5662) -> (-113.3051, -124.2447)
  curve K28 (-100.312, -123.6585) -> (-99.3992, -122.9747)
  line L43 (-101.582, -123.4631) -> (-100.312, -123.6585)
  curve K29 (-99.2527, -121.9001) -> (-101.582, -123.4631)
  curve K30 (-96.9905, -124.034) -> (-99.2527, -121.9001)
  line L44 (-96.9905, -125.7452) -> (-96.9905, -124.034)
  curve K31 (-96.5997, -127.5662) -> (-96.9905, -125.7452)
  line L45 (-98.0651, -127.5662) -> (-96.5997, -127.5662)
  curve K32 (-98.204, -127.0991) -> (-98.0651, -127.5662)
  curve K33 (-98.2559, -126.9144) -> (-98.204, -127.0991)
  curve K34 (-99.9549, -127.6639) -> (-98.2559, -126.9144)
  curve K35 (-101.7774, -125.9955) -> (-99.9549, -127.6639)
  curve K36 (-99.8297, -124.2203) -> (-101.7774, -125.9955)
  curve K37 (-98.4559, -123.8539) -> (-99.8297, -124.2203)
  line L46 (-98.4559, -123.715) -> (-98.4559, -123.8539)
  curve K38 (-99.3992, -122.9747) -> (-98.4559, -123.715)
  curve K39 (-88.7844, -125.8078) -> (-89.7246, -126.5893)
  line L47 (-87.319, -126.0031) -> (-88.7844, -125.8078)
  curve K40 (-89.7216, -127.6639) -> (-87.319, -126.0031)
  curve K41 (-91.8525, -126.7236) -> (-89.7216, -127.6639)
  curve K42 (-92.399, -124.8232) -> (-91.8525, -126.7236)
  curve K43 (-89.8574, -121.9001) -> (-92.399, -124.8232)
  curve K44 (-87.2213, -125.2216) -> (-89.8574, -121.9001)
  line L48 (-90.9336, -125.2216) -> (-87.2213, -125.2216)
  curve K45 (-89.7246, -126.5893) -> (-90.9336, -125.2216)
  line L49 (-114.282, -184.7162) -> (-112.8167, -184.7162)
  line L50 (-114.282, -177.0962) -> (-114.282, -184.7162)
  line L51 (-111.8443, -177.0962) -> (-114.282, -177.0962)
  curve K46 (-110.037, -177.2122) -> (-111.8443, -177.0962)
  curve K47 (-108.5182, -179.4607) -> (-110.037, -177.2122)
  curve K48 (-110.2171, -181.7732) -> (-108.5182, -179.4607)
  curve K49 (-111.8138, -181.8831) -> (-110.2171, -181.7732)
  line L52 (-112.8167, -181.8831) -> (-111.8138, -181.8831)
  line L53 (-112.8167, -184.7162) -> (-112.8167, -181.8831)
  line L54 (-99.8083, -184.7162) -> (-98.3735, -184.7162)
  line L55 (-101.582, -179.1478) -> (-99.8083, -184.7162)
  line L56 (-100.1411, -179.1478) -> (-101.582, -179.1478)
  line L57 (-99.0909, -182.7975) -> (-100.1411, -179.1478)
  line L58 (-98.1323, -179.1478) -> (-99.0909, -182.7975)
  line L59 (-96.7051, -179.1478) -> (-98.1323, -179.1478)
  line L60 (-95.7694, -182.7975) -> (-96.7051, -179.1478)
  line L61 (-94.7161, -179.1478) -> (-95.7694, -182.7975)
  line L62 (-93.2782, -179.1478) -> (-94.7161, -179.1478)
  line L63 (-95.0473, -184.7162) -> (-93.2782, -179.1478)
  line L64 (-96.4624, -184.7162) -> (-95.0473, -184.7162)
  line L65 (-97.4301, -181.1352) -> (-96.4624, -184.7162)
  line L66 (-98.3735, -184.7162) -> (-97.4301, -181.1352)
  line L67 (-85.072, -184.7162) -> (-85.072, -183.0646)
  line L68 (-86.5374, -184.7162) -> (-85.072, -184.7162)
  line L69 (-86.5374, -179.1478) -> (-86.5374, -184.7162)
  line L70 (-85.072, -179.1478) -> (-86.5374, -179.1478)
  line L71 (-85.072, -179.9247) -> (-85.072, -179.1478)
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  point P132 (-72.0887, -70.1115)
  point P130 (-127.2387, -48.1281)
  coincident L5 P132
  coincident L7 P130
sketch "Sketch165" plane through (-12.9087, 0, 0) normal (-1, 0, 0) x axis (0, -1, 0)
  line L1 (-124.3873, 24.4213) -> (-76.1273, 24.4213)
  line L2 (-124.3873, 53.6313) -> (-124.3873, 24.4213)
  line L3 (-76.1273, 53.6313) -> (-124.3873, 53.6313)
  line L4 (-76.1273, 24.4213) -> (-76.1273, 53.6313)
  line L5 (-72.0887, 73.7538) -> (-72.0887, -226.7462)
  line L6 (-127.2387, 73.7538) -> (-72.0887, 73.7538)
  line L7 (-127.2387, -226.7462) -> (-127.2387, 73.7538)
  line L8 (-72.0887, -226.7462) -> (-127.2387, -226.7462)
  curve K1 (-89.2728, -182.9578) -> (-90.2131, -183.7393)
  line L9 (-87.8074, -183.1531) -> (-89.2728, -182.9578)
  curve K2 (-90.21, -184.8139) -> (-87.8074, -183.1531)
  curve K3 (-92.341, -183.8736) -> (-90.21, -184.8139)
  curve K4 (-92.8874, -181.9732) -> (-92.341, -183.8736)
  curve K5 (-90.3459, -179.0501) -> (-92.8874, -181.9732)
  curve K6 (-87.7097, -182.3716) -> (-90.3459, -179.0501)
  line L10 (-91.422, -182.3716) -> (-87.7097, -182.3716)
  curve K7 (-90.2131, -183.7393) -> (-91.422, -182.3716)
  curve K8 (-107.639, -181.8541) -> (-104.8013, -184.8139)
  curve K9 (-104.8105, -179.0501) -> (-107.639, -181.8541)
  curve K10 (-101.9728, -181.9167) -> (-104.8105, -179.0501)
  curve K11 (-104.8013, -184.8139) -> (-101.9728, -181.9167)
  line L11 (-84.5836, -127.5662) -> (-84.5836, -125.9146)
  line L12 (-86.049, -127.5662) -> (-84.5836, -127.5662)
  line L13 (-86.049, -121.9978) -> (-86.049, -127.5662)
  line L14 (-84.5836, -121.9978) -> (-86.049, -121.9978)
  line L15 (-84.5836, -122.7747) -> (-84.5836, -121.9978)
  curve K12 (-83.4769, -121.9001) -> (-84.5836, -122.7747)
  curve K13 (-82.6297, -122.2084) -> (-83.4769, -121.9001)
  line L16 (-82.9717, -123.6021) -> (-82.6297, -122.2084)
  curve K14 (-83.6372, -123.3655) -> (-82.9717, -123.6021)
  curve K15 (-84.5836, -125.9146) -> (-83.6372, -123.3655)
  line L17 (-92.7897, -121.9978) -> (-93.8644, -121.9978)
  line L18 (-92.7897, -123.0724) -> (-92.7897, -121.9978)
  line L19 (-93.8644, -123.0724) -> (-92.7897, -123.0724)
  line L20 (-93.8644, -125.4658) -> (-93.8644, -123.0724)
  curve K16 (-93.4461, -126.5893) -> (-93.8644, -125.4658)
  curve K17 (-92.8386, -126.4489) -> (-93.4461, -126.5893)
  line L21 (-92.692, -127.4701) -> (-92.8386, -126.4489)
  curve K18 (-93.8705, -127.6639) -> (-92.692, -127.4701)
  curve K19 (-95.2824, -126.5939) -> (-93.8705, -127.6639)
  curve K20 (-95.3297, -125.5391) -> (-95.2824, -126.5939)
  line L22 (-95.3297, -123.0724) -> (-95.3297, -125.5391)
  line L23 (-96.0136, -123.0724) -> (-95.3297, -123.0724)
  line L24 (-96.0136, -121.9978) -> (-96.0136, -123.0724)
  line L25 (-95.3297, -121.9978) -> (-96.0136, -121.9978)
  line L26 (-95.3297, -120.9231) -> (-95.3297, -121.9978)
  line L27 (-93.8644, -120.0439) -> (-95.3297, -120.9231)
  line L28 (-93.8644, -121.9978) -> (-93.8644, -120.0439)
  curve K21 (-104.0244, -125.8078) -> (-104.9646, -126.5893)
  line L29 (-102.559, -126.0031) -> (-104.0244, -125.8078)
  curve K22 (-104.9616, -127.6639) -> (-102.559, -126.0031)
  curve K23 (-107.0925, -126.7236) -> (-104.9616, -127.6639)
  curve K24 (-107.639, -124.8232) -> (-107.0925, -126.7236)
  curve K25 (-105.0974, -121.9001) -> (-107.639, -124.8232)
  curve K26 (-102.4613, -125.2216) -> (-105.0974, -121.9001)
  line L30 (-106.1736, -125.2216) -> (-102.4613, -125.2216)
  curve K27 (-104.9646, -126.5893) -> (-106.1736, -125.2216)
  line L31 (-114.7705, -127.5662) -> (-113.3051, -127.5662)
  line L32 (-114.7705, -119.9462) -> (-114.7705, -127.5662)
  line L33 (-113.3051, -119.9462) -> (-114.7705, -119.9462)
  line L34 (-113.3051, -122.9747) -> (-113.3051, -119.9462)
  line L35 (-110.179, -122.9747) -> (-113.3051, -122.9747)
  line L36 (-110.179, -119.9462) -> (-110.179, -122.9747)
  line L37 (-108.7136, -119.9462) -> (-110.179, -119.9462)
  line L38 (-108.7136, -127.5662) -> (-108.7136, -119.9462)
  line L39 (-110.179, -127.5662) -> (-108.7136, -127.5662)
  line L40 (-110.179, -124.2447) -> (-110.179, -127.5662)
  line L41 (-113.3051, -124.2447) -> (-110.179, -124.2447)
  line L42 (-113.3051, -127.5662) -> (-113.3051, -124.2447)
  curve K28 (-100.312, -123.6585) -> (-99.3992, -122.9747)
  line L43 (-101.582, -123.4631) -> (-100.312, -123.6585)
  curve K29 (-99.2527, -121.9001) -> (-101.582, -123.4631)
  curve K30 (-96.9905, -124.034) -> (-99.2527, -121.9001)
  line L44 (-96.9905, -125.7452) -> (-96.9905, -124.034)
  curve K31 (-96.5997, -127.5662) -> (-96.9905, -125.7452)
  line L45 (-98.0651, -127.5662) -> (-96.5997, -127.5662)
  curve K32 (-98.204, -127.0991) -> (-98.0651, -127.5662)
  curve K33 (-98.2559, -126.9144) -> (-98.204, -127.0991)
  curve K34 (-99.9549, -127.6639) -> (-98.2559, -126.9144)
  curve K35 (-101.7774, -125.9955) -> (-99.9549, -127.6639)
  curve K36 (-99.8297, -124.2203) -> (-101.7774, -125.9955)
  curve K37 (-98.4559, -123.8539) -> (-99.8297, -124.2203)
  line L46 (-98.4559, -123.715) -> (-98.4559, -123.8539)
  curve K38 (-99.3992, -122.9747) -> (-98.4559, -123.715)
  curve K39 (-88.7844, -125.8078) -> (-89.7246, -126.5893)
  line L47 (-87.319, -126.0031) -> (-88.7844, -125.8078)
  curve K40 (-89.7216, -127.6639) -> (-87.319, -126.0031)
  curve K41 (-91.8525, -126.7236) -> (-89.7216, -127.6639)
  curve K42 (-92.399, -124.8232) -> (-91.8525, -126.7236)
  curve K43 (-89.8574, -121.9001) -> (-92.399, -124.8232)
  curve K44 (-87.2213, -125.2216) -> (-89.8574, -121.9001)
  line L48 (-90.9336, -125.2216) -> (-87.2213, -125.2216)
  curve K45 (-89.7246, -126.5893) -> (-90.9336, -125.2216)
  line L49 (-114.282, -184.7162) -> (-112.8167, -184.7162)
  line L50 (-114.282, -177.0962) -> (-114.282, -184.7162)
  line L51 (-111.8443, -177.0962) -> (-114.282, -177.0962)
  curve K46 (-110.037, -177.2122) -> (-111.8443, -177.0962)
  curve K47 (-108.5182, -179.4607) -> (-110.037, -177.2122)
  curve K48 (-110.2171, -181.7732) -> (-108.5182, -179.4607)
  curve K49 (-111.8138, -181.8831) -> (-110.2171, -181.7732)
  line L52 (-112.8167, -181.8831) -> (-111.8138, -181.8831)
  line L53 (-112.8167, -184.7162) -> (-112.8167, -181.8831)
  line L54 (-99.8083, -184.7162) -> (-98.3735, -184.7162)
  line L55 (-101.582, -179.1478) -> (-99.8083, -184.7162)
  line L56 (-100.1411, -179.1478) -> (-101.582, -179.1478)
  line L57 (-99.0909, -182.7975) -> (-100.1411, -179.1478)
  line L58 (-98.1323, -179.1478) -> (-99.0909, -182.7975)
  line L59 (-96.7051, -179.1478) -> (-98.1323, -179.1478)
  line L60 (-95.7694, -182.7975) -> (-96.7051, -179.1478)
  line L61 (-94.7161, -179.1478) -> (-95.7694, -182.7975)
  line L62 (-93.2782, -179.1478) -> (-94.7161, -179.1478)
  line L63 (-95.0473, -184.7162) -> (-93.2782, -179.1478)
  line L64 (-96.4624, -184.7162) -> (-95.0473, -184.7162)
  line L65 (-97.4301, -181.1352) -> (-96.4624, -184.7162)
  line L66 (-98.3735, -184.7162) -> (-97.4301, -181.1352)
  line L67 (-85.072, -184.7162) -> (-85.072, -183.0646)
  line L68 (-86.5374, -184.7162) -> (-85.072, -184.7162)
  line L69 (-86.5374, -179.1478) -> (-86.5374, -184.7162)
  line L70 (-85.072, -179.1478) -> (-86.5374, -179.1478)
  line L71 (-85.072, -179.9247) -> (-85.072, -179.1478)
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  coincident L5
  coincident L7
  dimension "d519" Text1-Height = 9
